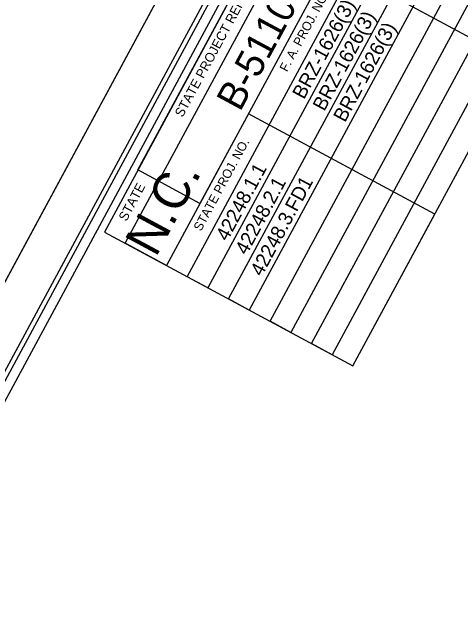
# Model space of a CAD drawing. Extents: x 1376167 to 1379209, y 761324 to 763997.
# Drawn here: x 1376804.3 to 1377042.5, y 763505 to 763833.3 of the extents above; entities that cross this region are included whole.
import ezdxf

# ---------------------------------------------------------------- set-up
doc = ezdxf.new("R2010")
doc.units = 0
for name, color, linetype in [('Sheet Cutting Line CELL', 7, 'Continuous'), ('Sheet Data Field CELL', 7, 'Continuous'), ('Sheet Plot Border Inside CELL', 7, 'Continuous'), ('Sheet Plot Border Outside CELL', 7, 'Continuous'), ('Sheet Title CELL', 7, 'Continuous')]:
    doc.layers.add(name, color=color, linetype=linetype)

msp = doc.modelspace()

# ---------------------------------------------------------------- linework, layer by layer
at = {"layer": 'Sheet Cutting Line CELL'}
msp.add_line((1376166.94, 762515.18), (1376966.07, 763997.49), dxfattribs=at)
at = {"layer": 'Sheet Plot Border Inside CELL'}
msp.add_lwpolyline([(1377121.6, 762015.28), (1377912.43, 763482.18), (1376983.7, 763982.88), (1376192.87, 762515.97)], close=True, dxfattribs=at)
at = {"layer": 'Sheet Plot Border Outside CELL'}
msp.add_lwpolyline([(1376966.07, 763997.49), (1376166.94, 762515.18), (1377135.18, 761993.19), (1377934.31, 763475.5)], close=True, dxfattribs=at)
at = {"layer": 'Sheet Title CELL'}
for points in [[(1376975.27, 763961.87), (1376272.92, 762659.12)], [(1376983.65, 763958.48), (1376853.16, 763716.41), (1376985.18, 763645.23), (1377028.69, 763725.9), (1376929.66, 763779.29), (1376903.96, 763731.62), (1376870.94, 763749.42), (1376948.08, 763892.47)], [(1376977.29, 763955.09), (1376303.44, 762705.17)], [(1377016.66, 763940.68), (1376886.16, 763698.62), (1376864.15, 763710.48), (1376994.65, 763952.55)], [(1377038.67, 763928.81), (1376908.17, 763686.75), (1376897.17, 763692.68), (1377027.67, 763934.74)], [(1377060.67, 763916.95), (1376930.17, 763674.89), (1376919.18, 763680.82), (1377049.67, 763922.89)], [(1377082.69, 763905.09), (1376952.19, 763663.03), (1376941.17, 763668.96), (1377071.67, 763911.02)], [(1377104.69, 763893.22), (1376974.18, 763651.16), (1376963.19, 763657.09), (1377093.69, 763899.15)], [(1376973.14, 763859.96), (1377072.17, 763806.58), (1377115.68, 763887.3)], [(1376985.18, 763645.23), (1377115.68, 763887.3)]]:
    msp.add_lwpolyline(points, dxfattribs=at)

# ---------------------------------------------------------------- texts
at = {"layer": 'Sheet Data Field CELL'}
for s, height, p in [('B-5110', 15, (1376925.25, 763779.95)), ('BRZ-1626(3)', 7.5, (1376959.2, 763786.56)), ('BRZ-1626(3)', 7.5, (1376970, 763780.25)), ('BRZ-1626(3)', 7.5, (1376980.99, 763774.33)), ('42248.1.1', 7.5, (1376918.53, 763711.11)), ('42248.2.1', 7.5, (1376928.77, 763703.77)), ('42248.3.FD1', 7.5, (1376936.81, 763692.38))]:
    msp.add_text(s, height=height, rotation=61.6702, dxfattribs=at).set_placement(p)
at = {"layer": 'Sheet Title CELL'}
for s, height, p in [('STATE PROJECT REFERENCE NO.', 4.9998, (1376894.67, 763777.08)), ('F. A. PROJ. NO.', 4.8, (1376950.19, 763801.28)), ('STATE PROJ. NO.', 4.8, (1376904.49, 763716.51)), ('N.C.', 19.35, (1376880.48, 763702.53)), ('STATE', 5, (1376864.84, 763721.76))]:
    msp.add_text(s, height=height, rotation=61.6702, dxfattribs=at).set_placement(p)

doc.saveas('drawing.dxf')
